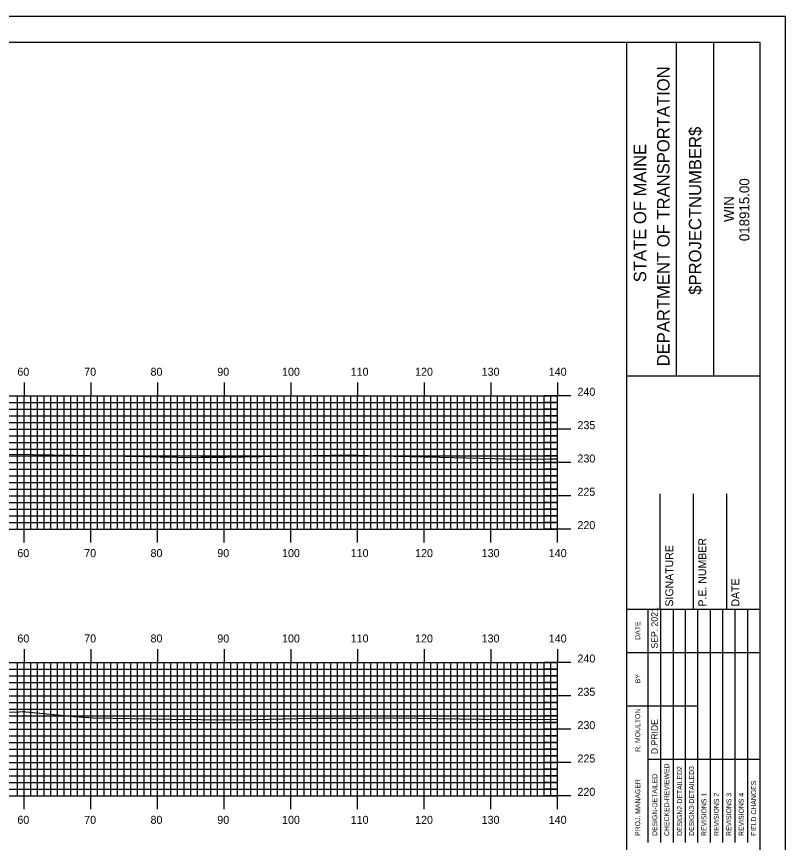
# Model space of a CAD drawing. Extents: x 1803110 to 1803453, y 442591 to 442811.
# Drawn here: x 1803334.5 to 1803449.8, y 442686.7 to 442810.5 of the extents above; entities that cross this region are included whole.
import ezdxf

# ---------------------------------------------------------------- set-up
doc = ezdxf.new("R2010")
doc.units = 0
for name, color, linetype in [('BORDER', 7, 'Continuous'), ('H_V ANNOTATION', 7, 'Continuous'), ('MAJOR', 7, 'Continuous'), ('MINOR', 7, 'Continuous'), ('PLOT BOUNDARY', 7, 'Continuous'), ('S_Roadway_Centerline', 7, 'Continuous')]:
    doc.layers.add(name, color=color, linetype=linetype)

msp = doc.modelspace()

# ---------------------------------------------------------------- linework, layer by layer
at = {"layer": 'BORDER'}
for p, q in [((1803426.03, 442596.67), (1803426.03, 442806.67)), ((1803433.48, 442756.66), (1803433.48, 442806.66)), ((1803439.08, 442756.66), (1803439.08, 442806.66)), ((1803426.03, 442756.65), (1803446.03, 442756.65)), ((1803431.03, 442721.67), (1803431.03, 442738.97)), ((1803436.03, 442721.67), (1803436.03, 442738.97)), ((1803441.03, 442721.67), (1803441.03, 442738.97)), ((1803426.03, 442721.67), (1803446.03, 442721.67))]:
    msp.add_line(p, q, dxfattribs=at)
msp.add_lwpolyline([(1803126.03, 442596.67), (1803446.03, 442596.67), (1803446.03, 442806.67), (1803126.03, 442806.67)], close=True, dxfattribs=at)
for points in [[(1803429.26, 442715.17), (1803429.26, 442721.67)], [(1803431.12, 442686.68), (1803431.12, 442721.67)], [(1803432.99, 442721.67), (1803432.99, 442686.68)], [(1803434.85, 442686.68), (1803434.85, 442721.67)], [(1803436.71, 442686.68), (1803436.71, 442721.67)], [(1803438.58, 442686.68), (1803438.58, 442721.67)], [(1803440.44, 442686.68), (1803440.44, 442721.67)], [(1803442.3, 442686.68), (1803442.3, 442721.67)], [(1803444.17, 442686.68), (1803444.17, 442721.67)], [(1803429.26, 442686.68), (1803429.26, 442720.26)], [(1803426.03, 442715.17), (1803446.03, 442715.17)], [(1803426.03, 442707.17), (1803429.26, 442707.17)], [(1803429.26, 442707.17), (1803436.71, 442707.17)], [(1803429.26, 442699.17), (1803446.03, 442699.17)]]:
    msp.add_lwpolyline(points, dxfattribs=at)
at = {"layer": 'MAJOR'}
for p, q in [((1803335.63, 442755.67), (1803335.63, 442753.67)), ((1803345.63, 442755.67), (1803345.63, 442753.67)), ((1803355.63, 442755.67), (1803355.63, 442753.67)), ((1803365.63, 442755.67), (1803365.63, 442753.67)), ((1803375.63, 442755.67), (1803375.63, 442753.67)), ((1803385.63, 442755.67), (1803385.63, 442753.67)), ((1803395.63, 442755.67), (1803395.63, 442753.67)), ((1803405.63, 442755.67), (1803405.63, 442753.67)), ((1803415.63, 442755.67), (1803415.63, 442753.67)), ((1803135.63, 442753.67), (1803415.63, 442753.67)), ((1803135.63, 442753.67), (1803415.63, 442753.67)), ((1803335.63, 442733.67), (1803335.63, 442753.67)), ((1803345.63, 442733.67), (1803345.63, 442753.67)), ((1803355.63, 442733.67), (1803355.63, 442753.67)), ((1803365.63, 442733.67), (1803365.63, 442753.67)), ((1803375.63, 442733.67), (1803375.63, 442753.67)), ((1803385.63, 442733.67), (1803385.63, 442753.67)), ((1803395.63, 442733.67), (1803395.63, 442753.67)), ((1803405.63, 442733.67), (1803405.63, 442753.67)), ((1803417.63, 442753.67), (1803413.62, 442753.67)), ((1803415.63, 442733.67), (1803415.63, 442753.67)), ((1803415.63, 442733.67), (1803415.63, 442753.67)), ((1803135.63, 442748.67), (1803415.63, 442748.67)), ((1803417.63, 442748.67), (1803413.62, 442748.67)), ((1803135.63, 442743.67), (1803415.63, 442743.67)), ((1803417.63, 442743.67), (1803413.62, 442743.67)), ((1803135.63, 442738.67), (1803415.63, 442738.67)), ((1803417.63, 442738.67), (1803413.62, 442738.67)), ((1803135.63, 442733.67), (1803415.63, 442733.67)), ((1803135.63, 442733.67), (1803415.63, 442733.67)), ((1803335.63, 442731.66), (1803335.63, 442733.67)), ((1803345.63, 442731.66), (1803345.63, 442733.67)), ((1803355.63, 442731.66), (1803355.63, 442733.67)), ((1803365.63, 442731.66), (1803365.63, 442733.67)), ((1803375.63, 442731.66), (1803375.63, 442733.67)), ((1803385.63, 442731.66), (1803385.63, 442733.67)), ((1803395.63, 442731.66), (1803395.63, 442733.67)), ((1803405.63, 442731.66), (1803405.63, 442733.67)), ((1803417.63, 442733.67), (1803413.62, 442733.67)), ((1803415.63, 442731.66), (1803415.63, 442733.67)), ((1803335.63, 442715.67), (1803335.63, 442713.67)), ((1803345.63, 442715.67), (1803345.63, 442713.67)), ((1803355.63, 442715.67), (1803355.63, 442713.67)), ((1803365.63, 442715.67), (1803365.63, 442713.67)), ((1803375.63, 442715.67), (1803375.63, 442713.67)), ((1803385.63, 442715.67), (1803385.63, 442713.67)), ((1803395.63, 442715.67), (1803395.63, 442713.67)), ((1803405.63, 442715.67), (1803405.63, 442713.67)), ((1803415.63, 442715.67), (1803415.63, 442713.67)), ((1803135.63, 442713.67), (1803415.63, 442713.67)), ((1803135.63, 442713.67), (1803415.63, 442713.67)), ((1803335.63, 442693.67), (1803335.63, 442713.67)), ((1803345.63, 442693.67), (1803345.63, 442713.67)), ((1803355.63, 442693.67), (1803355.63, 442713.67)), ((1803365.63, 442693.67), (1803365.63, 442713.67)), ((1803375.63, 442693.67), (1803375.63, 442713.67)), ((1803385.63, 442693.67), (1803385.63, 442713.67)), ((1803395.63, 442693.67), (1803395.63, 442713.67)), ((1803405.63, 442693.67), (1803405.63, 442713.67)), ((1803417.63, 442713.67), (1803413.62, 442713.67)), ((1803415.63, 442693.67), (1803415.63, 442713.67)), ((1803415.63, 442693.67), (1803415.63, 442713.67)), ((1803135.63, 442708.67), (1803415.63, 442708.67)), ((1803417.63, 442708.67), (1803413.62, 442708.67)), ((1803135.63, 442703.67), (1803415.63, 442703.67)), ((1803417.63, 442703.67), (1803413.62, 442703.67)), ((1803135.63, 442698.67), (1803415.63, 442698.67)), ((1803417.63, 442698.67), (1803413.62, 442698.67)), ((1803135.63, 442693.67), (1803415.63, 442693.67)), ((1803135.63, 442693.67), (1803415.63, 442693.67)), ((1803335.63, 442691.66), (1803335.63, 442693.67)), ((1803345.63, 442691.66), (1803345.63, 442693.67)), ((1803355.63, 442691.66), (1803355.63, 442693.67)), ((1803365.63, 442691.66), (1803365.63, 442693.67)), ((1803375.63, 442691.66), (1803375.63, 442693.67)), ((1803385.63, 442691.66), (1803385.63, 442693.67)), ((1803395.63, 442691.66), (1803395.63, 442693.67)), ((1803405.63, 442691.66), (1803405.63, 442693.67)), ((1803417.63, 442693.67), (1803413.62, 442693.67)), ((1803415.63, 442691.66), (1803415.63, 442693.67))]:
    msp.add_line(p, q, dxfattribs=at)
at = {"layer": 'MINOR'}
for p, q in [((1803334.63, 442733.67), (1803334.63, 442753.67)), ((1803336.63, 442733.67), (1803336.63, 442753.67)), ((1803337.63, 442733.67), (1803337.63, 442753.67)), ((1803338.63, 442733.67), (1803338.63, 442753.67)), ((1803339.63, 442733.67), (1803339.63, 442753.67)), ((1803340.63, 442733.67), (1803340.63, 442753.67)), ((1803341.63, 442733.67), (1803341.63, 442753.67)), ((1803342.63, 442733.67), (1803342.63, 442753.67)), ((1803343.63, 442733.67), (1803343.63, 442753.67)), ((1803344.63, 442733.67), (1803344.63, 442753.67)), ((1803346.63, 442733.67), (1803346.63, 442753.67)), ((1803347.63, 442733.67), (1803347.63, 442753.67)), ((1803348.63, 442733.67), (1803348.63, 442753.67)), ((1803349.63, 442733.67), (1803349.63, 442753.67)), ((1803350.63, 442733.67), (1803350.63, 442753.67)), ((1803351.63, 442733.67), (1803351.63, 442753.67)), ((1803352.63, 442733.67), (1803352.63, 442753.67)), ((1803353.63, 442733.67), (1803353.63, 442753.67)), ((1803354.63, 442733.67), (1803354.63, 442753.67)), ((1803356.63, 442733.67), (1803356.63, 442753.67)), ((1803357.63, 442733.67), (1803357.63, 442753.67)), ((1803358.63, 442733.67), (1803358.63, 442753.67)), ((1803359.63, 442733.67), (1803359.63, 442753.67)), ((1803360.63, 442733.67), (1803360.63, 442753.67)), ((1803361.63, 442733.67), (1803361.63, 442753.67)), ((1803362.63, 442733.67), (1803362.63, 442753.67)), ((1803363.63, 442733.67), (1803363.63, 442753.67)), ((1803364.63, 442733.67), (1803364.63, 442753.67)), ((1803366.63, 442733.67), (1803366.63, 442753.67)), ((1803367.63, 442733.67), (1803367.63, 442753.67)), ((1803368.63, 442733.67), (1803368.63, 442753.67)), ((1803369.63, 442733.67), (1803369.63, 442753.67)), ((1803370.63, 442733.67), (1803370.63, 442753.67)), ((1803371.63, 442733.67), (1803371.63, 442753.67)), ((1803372.63, 442733.67), (1803372.63, 442753.67)), ((1803373.63, 442733.67), (1803373.63, 442753.67)), ((1803374.63, 442733.67), (1803374.63, 442753.67)), ((1803376.63, 442733.67), (1803376.63, 442753.67)), ((1803377.63, 442733.67), (1803377.63, 442753.67)), ((1803378.63, 442733.67), (1803378.63, 442753.67)), ((1803379.63, 442733.67), (1803379.63, 442753.67)), ((1803380.63, 442733.67), (1803380.63, 442753.67)), ((1803381.63, 442733.67), (1803381.63, 442753.67)), ((1803382.63, 442733.67), (1803382.63, 442753.67)), ((1803383.63, 442733.67), (1803383.63, 442753.67)), ((1803384.63, 442733.67), (1803384.63, 442753.67)), ((1803386.63, 442733.67), (1803386.63, 442753.67)), ((1803387.63, 442733.67), (1803387.63, 442753.67)), ((1803388.63, 442733.67), (1803388.63, 442753.67)), ((1803389.63, 442733.67), (1803389.63, 442753.67)), ((1803390.63, 442733.67), (1803390.63, 442753.67)), ((1803391.63, 442733.67), (1803391.63, 442753.67)), ((1803392.63, 442733.67), (1803392.63, 442753.67)), ((1803393.63, 442733.67), (1803393.63, 442753.67)), ((1803394.63, 442733.67), (1803394.63, 442753.67)), ((1803396.63, 442733.67), (1803396.63, 442753.67)), ((1803397.63, 442733.67), (1803397.63, 442753.67)), ((1803398.63, 442733.67), (1803398.63, 442753.67)), ((1803399.63, 442733.67), (1803399.63, 442753.67)), ((1803400.63, 442733.67), (1803400.63, 442753.67)), ((1803401.63, 442733.67), (1803401.63, 442753.67)), ((1803402.63, 442733.67), (1803402.63, 442753.67)), ((1803403.63, 442733.67), (1803403.63, 442753.67)), ((1803404.63, 442733.67), (1803404.63, 442753.67)), ((1803406.63, 442733.67), (1803406.63, 442753.67)), ((1803407.63, 442733.67), (1803407.63, 442753.67)), ((1803408.63, 442733.67), (1803408.63, 442753.67)), ((1803409.63, 442733.67), (1803409.63, 442753.67)), ((1803410.63, 442733.67), (1803410.63, 442753.67)), ((1803411.63, 442733.67), (1803411.63, 442753.67)), ((1803412.63, 442733.67), (1803412.63, 442753.67)), ((1803413.63, 442733.67), (1803413.63, 442753.67)), ((1803414.63, 442733.67), (1803414.63, 442753.67)), ((1803135.63, 442752.67), (1803415.63, 442752.67)), ((1803415.63, 442752.67), (1803413.62, 442752.67)), ((1803135.63, 442751.67), (1803415.63, 442751.67)), ((1803415.63, 442751.67), (1803413.62, 442751.67)), ((1803135.63, 442750.67), (1803415.63, 442750.67)), ((1803415.63, 442750.67), (1803413.62, 442750.67)), ((1803135.63, 442749.67), (1803415.63, 442749.67)), ((1803415.63, 442749.67), (1803413.62, 442749.67)), ((1803135.63, 442747.67), (1803415.63, 442747.67)), ((1803415.63, 442747.67), (1803413.62, 442747.67)), ((1803135.63, 442746.67), (1803415.63, 442746.67)), ((1803415.63, 442746.67), (1803413.62, 442746.67)), ((1803135.63, 442745.67), (1803415.63, 442745.67)), ((1803415.63, 442745.67), (1803413.62, 442745.67)), ((1803135.63, 442744.67), (1803415.63, 442744.67)), ((1803415.63, 442744.67), (1803413.62, 442744.67)), ((1803135.63, 442742.67), (1803415.63, 442742.67)), ((1803415.63, 442742.67), (1803413.62, 442742.67)), ((1803135.63, 442741.67), (1803415.63, 442741.67)), ((1803415.63, 442741.67), (1803413.62, 442741.67)), ((1803135.63, 442740.67), (1803415.63, 442740.67)), ((1803415.63, 442740.67), (1803413.62, 442740.67)), ((1803135.63, 442739.67), (1803415.63, 442739.67)), ((1803415.63, 442739.67), (1803413.62, 442739.67)), ((1803135.63, 442737.67), (1803415.63, 442737.67)), ((1803415.63, 442737.67), (1803413.62, 442737.67)), ((1803135.63, 442736.67), (1803415.63, 442736.67)), ((1803415.63, 442736.67), (1803413.62, 442736.67)), ((1803135.63, 442735.67), (1803415.63, 442735.67)), ((1803415.63, 442735.67), (1803413.62, 442735.67)), ((1803135.63, 442734.67), (1803415.63, 442734.67)), ((1803415.63, 442734.67), (1803413.62, 442734.67)), ((1803334.63, 442693.67), (1803334.63, 442713.67)), ((1803336.63, 442693.67), (1803336.63, 442713.67)), ((1803337.63, 442693.67), (1803337.63, 442713.67)), ((1803338.63, 442693.67), (1803338.63, 442713.67)), ((1803339.63, 442693.67), (1803339.63, 442713.67)), ((1803340.63, 442693.67), (1803340.63, 442713.67)), ((1803341.63, 442693.67), (1803341.63, 442713.67)), ((1803342.63, 442693.67), (1803342.63, 442713.67)), ((1803343.63, 442693.67), (1803343.63, 442713.67)), ((1803344.63, 442693.67), (1803344.63, 442713.67)), ((1803346.63, 442693.67), (1803346.63, 442713.67)), ((1803347.63, 442693.67), (1803347.63, 442713.67)), ((1803348.63, 442693.67), (1803348.63, 442713.67)), ((1803349.63, 442693.67), (1803349.63, 442713.67)), ((1803350.63, 442693.67), (1803350.63, 442713.67)), ((1803351.63, 442693.67), (1803351.63, 442713.67)), ((1803352.63, 442693.67), (1803352.63, 442713.67)), ((1803353.63, 442693.67), (1803353.63, 442713.67)), ((1803354.63, 442693.67), (1803354.63, 442713.67)), ((1803356.63, 442693.67), (1803356.63, 442713.67)), ((1803357.63, 442693.67), (1803357.63, 442713.67)), ((1803358.63, 442693.67), (1803358.63, 442713.67)), ((1803359.63, 442693.67), (1803359.63, 442713.67)), ((1803360.63, 442693.67), (1803360.63, 442713.67)), ((1803361.63, 442693.67), (1803361.63, 442713.67)), ((1803362.63, 442693.67), (1803362.63, 442713.67)), ((1803363.63, 442693.67), (1803363.63, 442713.67)), ((1803364.63, 442693.67), (1803364.63, 442713.67)), ((1803366.63, 442693.67), (1803366.63, 442713.67)), ((1803367.63, 442693.67), (1803367.63, 442713.67)), ((1803368.63, 442693.67), (1803368.63, 442713.67)), ((1803369.63, 442693.67), (1803369.63, 442713.67)), ((1803370.63, 442693.67), (1803370.63, 442713.67)), ((1803371.63, 442693.67), (1803371.63, 442713.67)), ((1803372.63, 442693.67), (1803372.63, 442713.67)), ((1803373.63, 442693.67), (1803373.63, 442713.67)), ((1803374.63, 442693.67), (1803374.63, 442713.67)), ((1803376.63, 442693.67), (1803376.63, 442713.67)), ((1803377.63, 442693.67), (1803377.63, 442713.67)), ((1803378.63, 442693.67), (1803378.63, 442713.67)), ((1803379.63, 442693.67), (1803379.63, 442713.67)), ((1803380.63, 442693.67), (1803380.63, 442713.67)), ((1803381.63, 442693.67), (1803381.63, 442713.67)), ((1803382.63, 442693.67), (1803382.63, 442713.67)), ((1803383.63, 442693.67), (1803383.63, 442713.67)), ((1803384.63, 442693.67), (1803384.63, 442713.67)), ((1803386.63, 442693.67), (1803386.63, 442713.67)), ((1803387.63, 442693.67), (1803387.63, 442713.67)), ((1803388.63, 442693.67), (1803388.63, 442713.67)), ((1803389.63, 442693.67), (1803389.63, 442713.67)), ((1803390.63, 442693.67), (1803390.63, 442713.67)), ((1803391.63, 442693.67), (1803391.63, 442713.67)), ((1803392.63, 442693.67), (1803392.63, 442713.67)), ((1803393.63, 442693.67), (1803393.63, 442713.67)), ((1803394.63, 442693.67), (1803394.63, 442713.67)), ((1803396.63, 442693.67), (1803396.63, 442713.67)), ((1803397.63, 442693.67), (1803397.63, 442713.67)), ((1803398.63, 442693.67), (1803398.63, 442713.67)), ((1803399.63, 442693.67), (1803399.63, 442713.67)), ((1803400.63, 442693.67), (1803400.63, 442713.67)), ((1803401.63, 442693.67), (1803401.63, 442713.67)), ((1803402.63, 442693.67), (1803402.63, 442713.67)), ((1803403.63, 442693.67), (1803403.63, 442713.67)), ((1803404.63, 442693.67), (1803404.63, 442713.67)), ((1803406.63, 442693.67), (1803406.63, 442713.67)), ((1803407.63, 442693.67), (1803407.63, 442713.67)), ((1803408.63, 442693.67), (1803408.63, 442713.67)), ((1803409.63, 442693.67), (1803409.63, 442713.67)), ((1803410.63, 442693.67), (1803410.63, 442713.67)), ((1803411.63, 442693.67), (1803411.63, 442713.67)), ((1803412.63, 442693.67), (1803412.63, 442713.67)), ((1803413.63, 442693.67), (1803413.63, 442713.67)), ((1803414.63, 442693.67), (1803414.63, 442713.67)), ((1803135.63, 442712.67), (1803415.63, 442712.67)), ((1803135.63, 442711.67), (1803415.63, 442711.67)), ((1803415.63, 442712.67), (1803413.62, 442712.67)), ((1803415.63, 442711.67), (1803413.62, 442711.67)), ((1803135.63, 442710.67), (1803415.63, 442710.67)), ((1803415.63, 442710.67), (1803413.62, 442710.67)), ((1803135.63, 442709.67), (1803415.63, 442709.67)), ((1803415.63, 442709.67), (1803413.62, 442709.67)), ((1803135.63, 442707.67), (1803415.63, 442707.67)), ((1803135.63, 442706.67), (1803415.63, 442706.67)), ((1803415.63, 442707.67), (1803413.62, 442707.67)), ((1803415.63, 442706.67), (1803413.62, 442706.67)), ((1803135.63, 442705.67), (1803415.63, 442705.67)), ((1803415.63, 442705.67), (1803413.62, 442705.67)), ((1803135.63, 442704.67), (1803415.63, 442704.67)), ((1803415.63, 442704.67), (1803413.62, 442704.67)), ((1803135.63, 442702.67), (1803415.63, 442702.67)), ((1803135.63, 442701.67), (1803415.63, 442701.67)), ((1803415.63, 442702.67), (1803413.62, 442702.67)), ((1803415.63, 442701.67), (1803413.62, 442701.67)), ((1803135.63, 442700.67), (1803415.63, 442700.67)), ((1803415.63, 442700.67), (1803413.62, 442700.67)), ((1803135.63, 442699.67), (1803415.63, 442699.67)), ((1803415.63, 442699.67), (1803413.62, 442699.67)), ((1803135.63, 442697.67), (1803415.63, 442697.67)), ((1803135.63, 442696.67), (1803415.63, 442696.67)), ((1803415.63, 442697.67), (1803413.62, 442697.67)), ((1803415.63, 442696.67), (1803413.62, 442696.67)), ((1803135.63, 442695.67), (1803415.63, 442695.67)), ((1803415.63, 442695.67), (1803413.62, 442695.67)), ((1803135.63, 442694.67), (1803415.63, 442694.67)), ((1803415.63, 442694.67), (1803413.62, 442694.67))]:
    msp.add_line(p, q, dxfattribs=at)
at = {"layer": 'PLOT BOUNDARY'}
msp.add_lwpolyline([(1803109.84, 442590.55), (1803449.84, 442590.55), (1803449.84, 442810.55), (1803109.84, 442810.55)], close=True, dxfattribs=at)
at = {"layer": 'S_Roadway_Centerline'}
for points in [[(1803328.89, 442744.95), (1803336.93, 442744.86), (1803343.01, 442744.75), (1803361.21, 442744.43), (1803362.18, 442744.44), (1803365.91, 442744.48), (1803384.22, 442744.8), (1803388.82, 442744.64), (1803397.96, 442744.45), (1803406.09, 442744.24), (1803409.82, 442744.18), (1803414.45, 442744.19), (1803415.63, 442744.2)], [(1803330.37, 442706.2), (1803334.86, 442706.27), (1803335.36, 442706.33), (1803343.13, 442705.58), (1803345.98, 442705.38), (1803357.69, 442705.19), (1803366.63, 442705.05), (1803370.06, 442705.12), (1803378.78, 442705.33), (1803385.91, 442705.34), (1803391.72, 442705.38), (1803397.71, 442705.27), (1803407.51, 442705.13), (1803412.23, 442705.18), (1803415.63, 442705.14)]]:
    msp.add_lwpolyline(points, dxfattribs=at)

# ---------------------------------------------------------------- texts
at = {"layer": 'BORDER'}
for s, height, p in [('DEPARTMENT OF TRANSPORTATION', 1.8635, (1803432.44, 442758.08)), ('$PROJECTNUMBER$', 1.8635, (1803437.21, 442768.82)), ('STATE OF MAINE', 1.8635, (1803428.94, 442770.69)), ('018915.00', 1.491, (1803444.42, 442776.86)), ('WIN', 1.491, (1803442.1, 442779.73)), ('P.E. NUMBER', 1.1811, (1803437.95, 442722.06)), ('SIGNATURE', 1.181, (1803432.99, 442722.06)), ('DATE', 1.181, (1803442.91, 442722.06)), ('SEP. 2021', 0.969, (1803430.67, 442715.76)), ('DATE', 0.743, (1803428.04, 442717.08)), ('BY', 0.743, (1803428.04, 442710.54)), ('R. MOULTON', 0.745, (1803428.04, 442700.28)), ('D.PRIDE', 0.969, (1803430.67, 442699.92)), ('CHECKED-REVIEWED', 0.7455, (1803432.39, 442687.65)), ('DESIGN2-DETAILED2', 0.7455, (1803434.33, 442687.65)), ('DESIGN3-DETAILED3', 0.7455, (1803436.12, 442687.65)), ('PROJ. MANAGER', 0.7455, (1803428.04, 442687.65)), ('DESIGN-DETAILED', 0.7455, (1803430.6, 442687.65)), ('FIELD CHANGES', 0.7455, (1803445.43, 442687.65)), ('REVISIONS 1', 0.7455, (1803437.98, 442687.65)), ('REVISIONS 2', 0.7455, (1803439.84, 442687.65)), ('REVISIONS 3', 0.7455, (1803441.71, 442687.65)), ('REVISIONS 4', 0.7455, (1803443.57, 442687.65))]:
    msp.add_text(s, height=height, rotation=90, dxfattribs=at).set_placement(p)
at = {"layer": 'H_V ANNOTATION'}
for s, p in [('60', (1803334.6, 442756.67)), ('70', (1803344.63, 442756.67)), ('80', (1803354.58, 442756.67)), ('90', (1803364.6, 442756.67)), ('100', (1803374.31, 442756.67)), ('110', (1803384.61, 442756.67)), ('120', (1803394.27, 442756.67)), ('130', (1803404.26, 442756.67)), ('140', (1803414.33, 442756.67)), ('240', (1803418.63, 442753.67)), ('235', (1803418.63, 442748.67)), ('230', (1803418.63, 442743.67)), ('225', (1803418.63, 442738.67)), ('220', (1803418.63, 442733.67)), ('60', (1803334.6, 442729.47)), ('70', (1803344.63, 442729.47)), ('80', (1803354.58, 442729.47)), ('90', (1803364.6, 442729.47)), ('100', (1803374.31, 442729.47)), ('110', (1803384.61, 442729.47)), ('120', (1803394.27, 442729.47)), ('130', (1803404.26, 442729.47)), ('140', (1803414.33, 442729.47)), ('60', (1803334.6, 442716.67)), ('70', (1803344.63, 442716.67)), ('80', (1803354.58, 442716.67)), ('90', (1803364.6, 442716.67)), ('100', (1803374.31, 442716.67)), ('110', (1803384.61, 442716.67)), ('120', (1803394.27, 442716.67)), ('130', (1803404.26, 442716.67)), ('140', (1803414.33, 442716.67)), ('240', (1803418.63, 442713.67)), ('235', (1803418.63, 442708.67)), ('230', (1803418.63, 442703.67)), ('225', (1803418.63, 442698.67)), ('220', (1803418.63, 442693.67)), ('60', (1803334.6, 442689.47)), ('70', (1803344.63, 442689.47)), ('80', (1803354.58, 442689.47)), ('90', (1803364.6, 442689.47)), ('100', (1803374.31, 442689.47)), ('110', (1803384.61, 442689.47)), ('120', (1803394.27, 442689.47)), ('130', (1803404.26, 442689.47)), ('140', (1803414.33, 442689.47))]:
    msp.add_text(s, height=1.2, dxfattribs=at).set_placement(p)

doc.saveas('drawing.dxf')
